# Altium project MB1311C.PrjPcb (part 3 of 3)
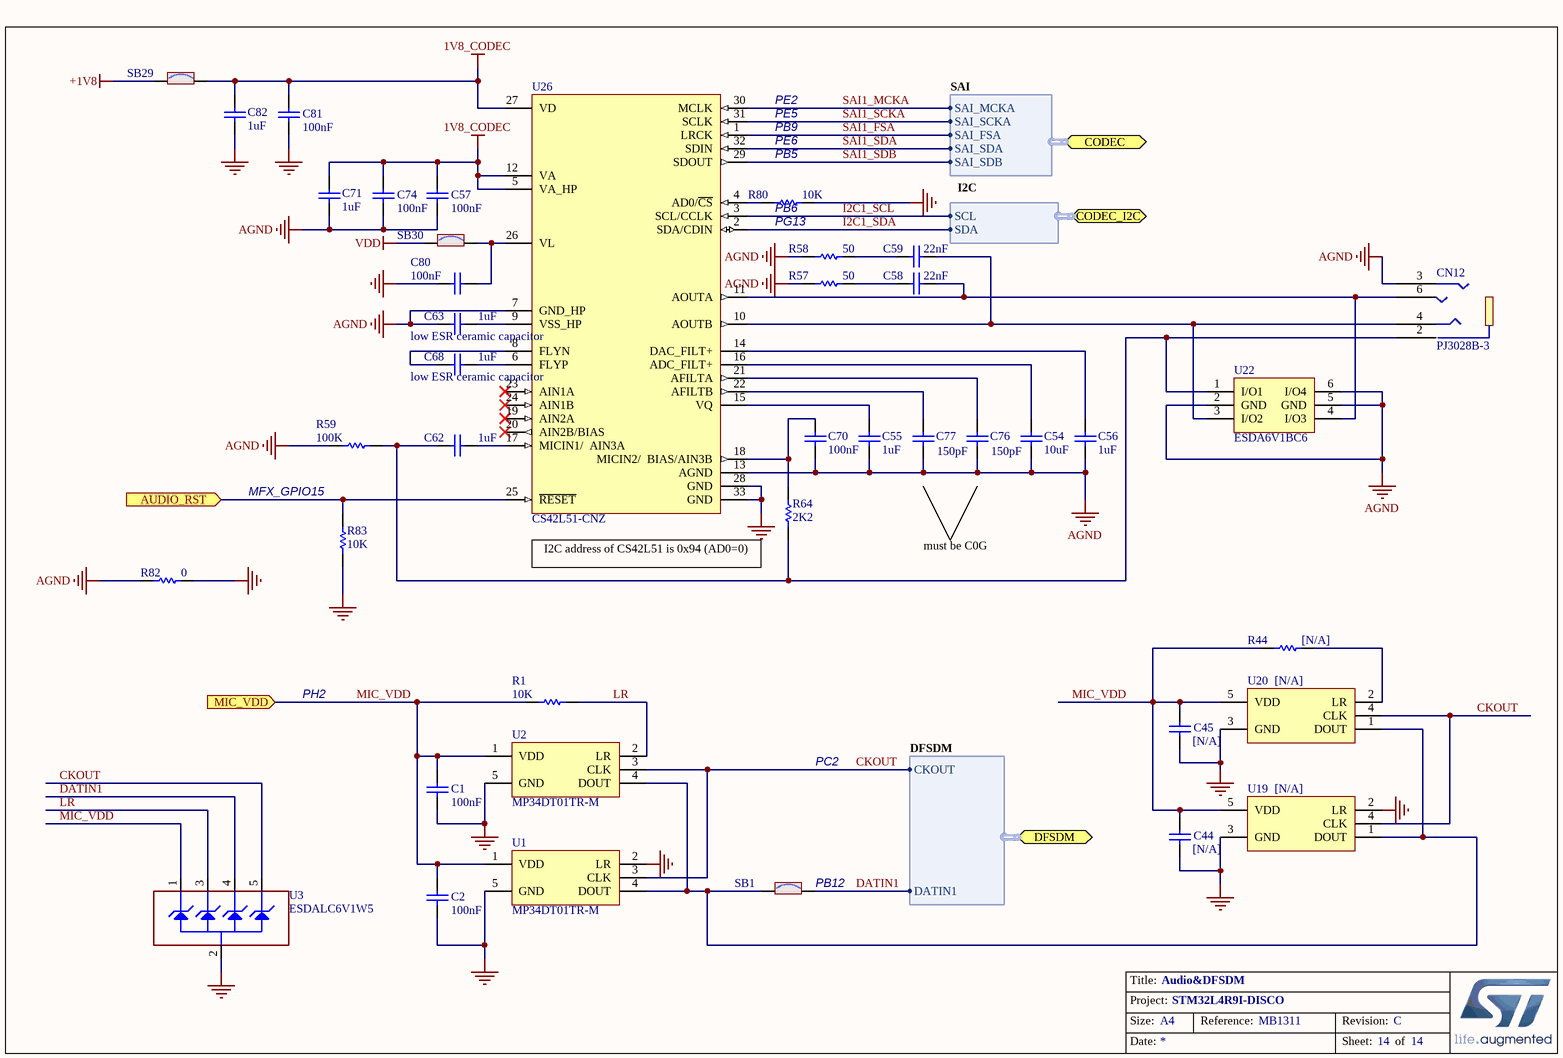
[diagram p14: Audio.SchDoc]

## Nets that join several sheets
1V8_LCD: LCD (7 pins), PSRAM (SB39.2)
5V_USB_CHARGER: Power (JP4.9), ST_LINK_V2-1_2 (12 pins)
+1V8: LCD (T6.4), Power (C30.1 JP7.3 L4.2 U9.C2), Audio (SB29.1)
+3V3: Arduino_ Connectors (CN16.4 R2.1), LCD (T4.4), MCU (JP3.1), Peripherals (LD1.1 LD2.1), Power (C38.1 JP7.1 L5.2 U14.C2), PSRAM (R11.2), USB_OTG_FS (R38.1 R39.1 R43.1), STMOD+ (CN3.6 CN3.12)
+5V: IDD_measurement (R90.2 T11.4), LCD (L2.1 R50.1), Peripherals (SB37.2), Power (18 pins), ST_LINK_V2-1_2 (SW1.6), USB_OTG_FS (R40.1 SB15.1), STMOD+ (CN1.6 CN1.15)
ARD_5V: Arduino_ Connectors (CN16.5), Power (JP5.2)
E5V: Arduino_ Connectors (R109.1), Power (C36.1 JP4.3 U15.2 U15.4), ST_LINK_V2-1_2 (D5.1)
GND: Arduino_ Connectors (6 pins), Camera (7 pins), IDD_measurement (25 pins), LCD (20 pins), MCU (46 pins), Peripherals (10 pins), Power (13 pins), PSRAM (7 pins), OCTOSPI (9 pins), ST_LINK_V2-1_2 (55 pins), USB_OTG_FS (12 pins), STMOD+ (8 pins), Audio (19 pins)
U5V_ST_LINK: Power (JP4.1), ST_LINK_V2-1_2 (5 pins)
VDD: Arduino_ Connectors (CN16.2), Camera (C3.1 C46.2 CN2.20 CN2.30), IDD_measurement (R74.2 R97.1 T9.4), LCD (T5.4), MCU (R16.1 R99.1 R100.1), Peripherals (5 pins), Power (JP7.2), OCTOSPI (SB23.1), ST_LINK_V2-1_2 (CN8.1 SW1.5), STMOD+ (C47.1 R46.2 U21.2), Audio (SB30.1)
VDD_LCD: LCD (7 pins), PSRAM (R13.2)
VDD_MCU: IDD_measurement (JP1.2 SB31.1), MCU (27 pins)
VIN: Arduino_ Connectors (CN16.8), Power (C39.1 U15.3)
VREF+: Arduino_ Connectors (C48.1 SB27.2), MCU (C13.1 C15.1 R14.1 U7.L1)
ARD_A0: Arduino_ Connectors (CN17.1), MCU (U7.M4)
ARD_A1: Arduino_ Connectors (CN17.2), MCU (U7.K4)
ARD_A2: Arduino_ Connectors (CN17.3), MCU (U7.K1)
ARD_A3: Arduino_ Connectors (CN17.4), LCD (SB7.2), MCU (U7.N4)
ARD_A4: Arduino_ Connectors (SB33.1), MCU (U7.K3)
ARD_A5: Arduino_ Connectors (SB35.1), MCU (U7.L3), STMOD+ (CN1.14)
ARD_D0: Arduino_ Connectors (CN11.1), MCU (U7.J2)
ARD_D1: Arduino_ Connectors (CN11.2), MCU (U7.J3)
ARD_D2: Arduino_ Connectors (CN11.3), MCU (U7.E6)
ARD_D3: Arduino_ Connectors (CN11.4), MCU (U7.H4)
ARD_D4: Arduino_ Connectors (CN11.5), MCU (U7.G12)
ARD_D5: Arduino_ Connectors (CN11.6), MCU (U7.M1)
ARD_D6: Arduino_ Connectors (CN11.7), MCU (U7.A5)
ARD_D7: Arduino_ Connectors (CN11.8), Camera (CN2.17), MCU (U7.N2), STMOD+ (CN1.13)
ARD_D8: Arduino_ Connectors (CN10.1), MCU (U7.B12)
ARD_D9: Arduino_ Connectors (CN10.2), MCU (U7.C9)
ARD_D10: Arduino_ Connectors (CN10.3), MCU (U7.A12)
ARD_D11: Arduino_ Connectors (CN10.4), LCD (SB6.2), MCU (U7.L10), STMOD+ (SB21.1 U21.1)
ARD_D12: Arduino_ Connectors (CN10.5), LCD (CN4.28), MCU (U7.M12), STMOD+ (SB17.1 U21.6)
ARD_D13: Arduino_ Connectors (CN10.6 SB2.2), LCD (SB8.2), MCU (U7.N13), STMOD+ (SB19.1 U21.14)
ARD_D14: Arduino_ Connectors (CN10.9 SB32.1), MCU (U7.F10), STMOD+ (CN1.10)
ARD_D15: Arduino_ Connectors (CN10.10 SB34.1), MCU (U7.G10), STMOD+ (CN1.7)
CKOUT: MCU (U7.J4), STMOD+ (CN1.18 CN1.20), Audio (5 pins)
D0: MCU (U7.H11), PSRAM (U5.B6 U6.B6)
D1: MCU (U7.H10), PSRAM (U5.C5 U6.C5)
D2: MCU (U7.B8), PSRAM (U5.C6 U6.C6)
D3: MCU (U7.C8), PSRAM (U5.D5 U6.D5)
D4: MCU (U7.L7), PSRAM (U5.E5 U6.E5)
D5: MCU (U7.K6), PSRAM (U5.F5 U6.F5)
D6: MCU (U7.J6), PSRAM (U5.F6 U6.F6)
D7: MCU (U7.H6), PSRAM (U5.G6 U6.G6)
D8: MCU (U7.N8), PSRAM (U5.B1 U6.B1)
D9: MCU (U7.M8), PSRAM (U5.C1 U6.C1)
D10: MCU (U7.L8), PSRAM (U5.C2 U6.C2)
D11: MCU (U7.K7), PSRAM (U5.D2 U6.D2)
D12: MCU (U7.J7), PSRAM (U5.E2 U6.E2)
D13: MCU (U7.K10), PSRAM (U5.F2 U6.F2)
D14: MCU (U7.K9), PSRAM (U5.F1 U6.F1)
D15: MCU (U7.J10), PSRAM (U5.G1 U6.G1)
D_N: MCU (U7.E13), USB_OTG_FS (CN9.2 U18.3)
D_P: MCU (U7.D13), USB_OTG_FS (CN9.3 U18.4)
DATIN1: MCU (U7.N12), STMOD+ (CN1.17), Audio (SB1.2 U3.4)
DCMI_CLK: Camera (R4.2), LCD (CN4.43), MCU (U7.E11)
DCMI_D0: Camera (CN2.4), MCU (U7.F11), STMOD+ (CN1.11 CN3.7)
DCMI_D1: Camera (CN2.5), MCU (U7.G11), STMOD+ (CN1.19)
DCMI_D2: Camera (CN2.6), MCU (U7.M10)
DCMI_D3: Camera (CN2.7), MCU (U7.B13)
DCMI_D4: Camera (CN2.8), MCU (U7.D1), PSRAM (SB3.1)
DCMI_D5: Camera (CN2.9), MCU (U7.D10)
DCMI_D6: Camera (CN2.10), MCU (U7.C4)
DCMI_D7: Camera (CN2.11), MCU (U7.B2), STMOD+ (CN1.12 CN3.8)
DCMI_I2C1_SCL: Camera (CN2.28), IDD_measurement (U29.42), LCD (CN4.44), MCU (R99.2 U7.C5), Peripherals (R107.1), Audio (U26.3)
DCMI_I2C1_SDA: Camera (CN2.27), IDD_measurement (U29.43), LCD (CN4.40), MCU (R100.2 U7.G6), Peripherals (R108.1), Audio (U26.2)
DCMI_NRST: Arduino_ Connectors (CN16.3), Camera (CN2.26), IDD_measurement (D3.2), MCU (C10.1 U7.H3), Peripherals (B1.3), OCTOSPI (SB24.1), ST_LINK_V2-1_2 (R115.2 SW1.7)
DCMI_PIXCLK: Camera (CN2.15), MCU (U7.L9)
DCMI_PWR_EN: Camera (CN2.25), IDD_measurement (U29.33)
DCMI_VSYNC: Camera (CN2.19), MCU (U7.E10)
DSI_BL_CTRL: LCD (CN4.53), MCU (U7.L5)
DSI_CK_N: LCD (CN4.5), MCU (U7.K12)
DSI_CK_P: LCD (CN4.3), MCU (U7.K11)
DSI_D0_N: LCD (CN4.11), MCU (U7.L12)
DSI_D0_P: LCD (CN4.9), MCU (U7.L11)
DSI_D1_N: LCD (CN4.17), MCU (U7.J12)
DSI_D1_P: LCD (CN4.15), MCU (U7.J11)
DSI_PWR_ON: IDD_measurement (R116.2 R117.2), LCD (R50.2 R118.2 R119.2 R120.2)
DSI_SPI_USART_CS: LCD (CN4.22), MCU (U7.A13)
DSI_TE: LCD (CN4.49), MCU (U7.M5)
JOY_DOWN: IDD_measurement (U29.20), Peripherals (B2.3 U17.5)
JOY_LEFT: IDD_measurement (U29.40), Peripherals (B2.1 U17.4)
JOY_RIGHT: IDD_measurement (U29.39), Peripherals (B2.6 U17.3)
JOY_SEL: MCU (U7.E1), Peripherals (B2.2 U4.2)
JOY_UP: IDD_measurement (U29.19), Peripherals (B2.4 U17.1)
LED_GREEN: MCU (U7.K8), Peripherals (R5.1)
MCO: MCU (SB28.2), ST_LINK_V2-1_2 (U30.29)
MFX_IRQ_OUT: IDD_measurement (U29.46), MCU (U7.B11)
MFX_WAKEUP: IDD_measurement (R87.2 U29.2), MCU (U7.N5)
MIC_VDD: MCU (U7.A2), Audio (11 pins)
NetCN4_57: IDD_measurement (U29.31), LCD (CN4.57 R7.2)
NetR3_1: IDD_measurement (U29.18), Peripherals (R3.1)
NetR41_2: IDD_measurement (U29.26), USB_OTG_FS (R41.2)
NetR83_2: IDD_measurement (U29.28), Audio (R83.2 U26.25)
NetR112_2: IDD_measurement (U29.32), Peripherals (R112.2)
OCTOSPIM_P2_CLK: MCU (U7.B9), OCTOSPI (R73.1)
OCTOSPIM_P2_CS: MCU (U7.F6), OCTOSPI (R51.1)
OCTOSPIM_P2_DQS: MCU (U7.C6), OCTOSPI (R52.1)
OCTOSPIM_P2_IO0: MCU (U7.C3), OCTOSPI (R68.1)
OCTOSPIM_P2_IO1: MCU (U7.A1), OCTOSPI (R71.1)
OCTOSPIM_P2_IO2: MCU (U7.B1), OCTOSPI (R53.1)
OCTOSPIM_P2_IO3: MCU (U7.N10), OCTOSPI (R78.1)
OCTOSPIM_P2_IO4: MCU (U7.C11), OCTOSPI (R67.1)
OCTOSPIM_P2_IO5: MCU (U7.M9), OCTOSPI (R72.1)
OCTOSPIM_P2_IO6: MCU (U7.B7), OCTOSPI (R69.1)
OCTOSPIM_P2_IO7: MCU (U7.D6), OCTOSPI (R63.1)
PMOD#1: MCU (U7.L4), STMOD+ (CN1.1 CN3.1)
PMOD_SEL_0: IDD_measurement (U29.16), STMOD+ (R46.1 U21.3)
PMOD_SEL_1: IDD_measurement (U29.17), STMOD+ (R45.2 U21.10)
PSRAM_A0: MCU (U7.F5), PSRAM (U5.A3 U6.A3)
PSRAM_A1: MCU (U7.F4), PSRAM (U5.A4 U6.A4)
PSRAM_A2: MCU (U7.F3), PSRAM (U5.A5 U6.A5)
PSRAM_A3: MCU (U7.G3), PSRAM (U5.B3 U6.B3)
PSRAM_A4: MCU (U7.G4), PSRAM (U5.B4 U6.B4)
PSRAM_A5: MCU (U7.G5), PSRAM (U5.C3 U6.C3)
PSRAM_A6: MCU (U7.N6), PSRAM (U5.C4 U6.C4)
PSRAM_A7: MCU (U7.M6), PSRAM (U5.D4 U6.D4)
PSRAM_A8: MCU (U7.L6), PSRAM (U5.H2 U6.H2)
PSRAM_A9: MCU (U7.K5), PSRAM (U5.H3 U6.H3)
PSRAM_A10: MCU (U7.J5), PSRAM (U5.H4 U6.H4)
PSRAM_A11: MCU (U7.H5), PSRAM (U5.H5 U6.H5)
PSRAM_A12: MCU (U7.H9), PSRAM (U5.G3 U6.G3)
PSRAM_A13: MCU (U7.G8), PSRAM (U5.G4 U6.G4)
PSRAM_A14: MCU (U7.G7), PSRAM (U5.F3 U6.F3)
PSRAM_A15: MCU (U7.G9), PSRAM (U5.F4 U6.F4)
PSRAM_A16: MCU (U7.J9), PSRAM (U5.E4 U6.E4)
PSRAM_A17: MCU (U7.J8), PSRAM (U5.D3 U6.D3)
PSRAM_A18: MCU (U7.H8), PSRAM (U5.H1 U6.H1)
PSRAM_A19: MCU (U7.D2), PSRAM (U5.G2 U6.G2)
PSRAM_ADV: MCU (U7.D5), PSRAM (U6.J3)
PSRAM_CLK: MCU (U7.E8), PSRAM (U6.J2)
PSRAM_NBL0: MCU (U7.A4), PSRAM (U5.A1 U6.A1)
PSRAM_NBL1: MCU (U7.B4), PSRAM (R9.2 U5.B2 U6.B2)
PSRAM_NE1: MCU (U7.F7), PSRAM (JP2.1 R17.2)
PSRAM_OE: MCU (U7.C7), PSRAM (U5.A2 U6.A2)
PSRAM_WAIT: MCU (U7.E7), PSRAM (U6.J1)
PSRAM_WE: MCU (U7.D7), PSRAM (U5.G5 U6.G5)
SAI1_FSA: MCU (U7.D4), Audio (U26.1)
SAI1_MCKA: MCU (U7.D3), Audio (U26.30)
SAI1_SCKA: MCU (U7.E4), Audio (U26.31)
SAI1_SDA: MCU (U7.E3), Audio (U26.32)
SAI1_SDB: MCU (U7.B5), Audio (U26.29)
SPI2_MISOs: MCU (U7.B10), STMOD+ (CN1.9)
SPI2_MOSIs: MCU (U7.C10), STMOD+ (CN1.8)
SWCLK: MCU (U7.A10), ST_LINK_V2-1_2 (R24.1 R26.2)
SWDIO: MCU (U7.A11), ST_LINK_V2-1_2 (R110.2 SW1.8)
SWO: MCU (U7.A6), ST_LINK_V2-1_2 (R31.1 R111.2)
TOUCH_INT: IDD_measurement (U29.30), LCD (CN4.4)
USART2_RX: MCU (U7.M2), ST_LINK_V2-1_2 (R88.2)
USART2_TX: MCU (U7.N1), ST_LINK_V2-1_2 (R20.1)
USART3_RTS: MCU (U7.A9), STMOD+ (SB18.1 U21.12)
USART3_RX: MCU (U7.H7), STMOD+ (SB16.1 U21.4)
USART3_TX: LCD (SB13.2), MCU (U7.N9), STMOD+ (SB20.1 U21.15)
USB_OTGFS_ID: MCU (U7.D11), USB_OTG_FS (CN9.4 U18.1)
USB_OTGFS_OVRCR: IDD_measurement (U29.27), USB_OTG_FS (LD7.2 R39.2 U16.3)
USB_OTGFS_VBUS: MCU (U7.E12), Power (JP4.5), ST_LINK_V2-1_2 (D6.1), USB_OTG_FS (5 pins)
uSD_CLK: MCU (U7.F8), Peripherals (U13.6)
uSD_CMD: MCU (U7.D8), Peripherals (U13.5)
uSD_D0: MCU (U7.F9), Peripherals (U13.7)
uSD_D1: MCU (U7.G13), Peripherals (U13.8)
uSD_D2: MCU (U7.D9), Peripherals (U13.3)
uSD_D3: MCU (U7.E9), Peripherals (U13.4)
uSD_Detect: IDD_measurement (U29.15), Peripherals (CN6.9 U13.1)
